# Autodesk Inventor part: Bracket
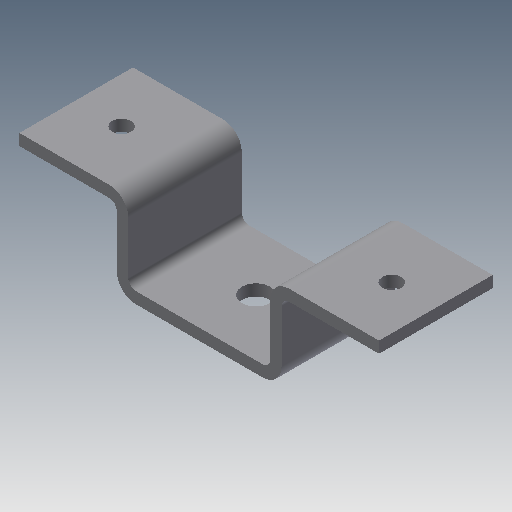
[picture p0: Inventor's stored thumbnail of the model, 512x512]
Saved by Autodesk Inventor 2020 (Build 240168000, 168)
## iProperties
Created: 2010-05
Part Number: Bracket
Document SubType Name: Modeling
Designer: CADSoft
Density: 1 g/cm^3
Material: Generic
Appearance: Default
Author: CADSoft
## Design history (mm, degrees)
sketch "Sketch1"
  geometry: L1 (-476.866, 0)-(-189.366, 0); L2 (-189.366, 0)-(-189.366, -208); L3 (-189.366, -208)-(185.634, -208); L4 (185.634, -208)-(185.634, 0); L5 (185.634, 0)-(473.134, 0); L6 (473.134, 0)-(473.134, -30); L7 (473.134, -30)-(215.634, -30); L8 (215.634, -30)-(215.634, -238); L9 (215.634, -238)-(-219.366, -238); L10 (-219.366, -238)-(-219.366, -30); L11 (-219.366, -30)-(-476.866, -30); L12 (-476.866, -30)-(-476.866, 0); 1 further point
  constraints: 24 end point, 8 parallel, 5 equal length, 1 collinear, 1 horizontal, 1 horizontal alignment, 1 perpendicular
  dimensions: "d0" = 950 distance between parallel lines of L6 L12; "d1" = 238 distance between parallel lines of L1 L9; "d2" = 30 distance of L5.end L6.end; "d3" = 30 distance between parallel lines of L9 L3; "d4" = 30 distance between parallel lines of L4 L8; "d5" = 435 distance of L8.end L9.end
extrude "Extrusion1" new body sketch "Sketch1" stored distance "d6" = 300; taper "d7" = 0 deg
fillet "Fillet1" dims "d8" = 20
fillet "Fillet2" dims "d9" = 50
hole "Hole1" diameter "d12" = 75; stored, may be unused: countersink angle "d16" = 90 deg, drill point angle "d18" = 118 deg; dims "d10" = 150, "d11" = 217.5, "d13" = 6, "d14" = 4, "d15" = 2, "d17" = 8
hole "Hole2" diameter "d21" = 50; stored, may be unused: countersink angle "d25" = 90 deg, drill point angle "d27" = 118 deg; dims "d19" = 150, "d20" = 120, "d22" = 6, "d23" = 4, "d24" = 2, "d26" = 8
mirror "Mirror1"
body "Solid1"
